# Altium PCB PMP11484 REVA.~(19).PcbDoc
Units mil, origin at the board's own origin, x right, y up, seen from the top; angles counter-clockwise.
Board outline 2400 x 2250 mil, 2 copper layers (Top Layer, Bottom Layer), stack 62 mil thick; 51 components, 24 nets, 109 pads, 73 vias.
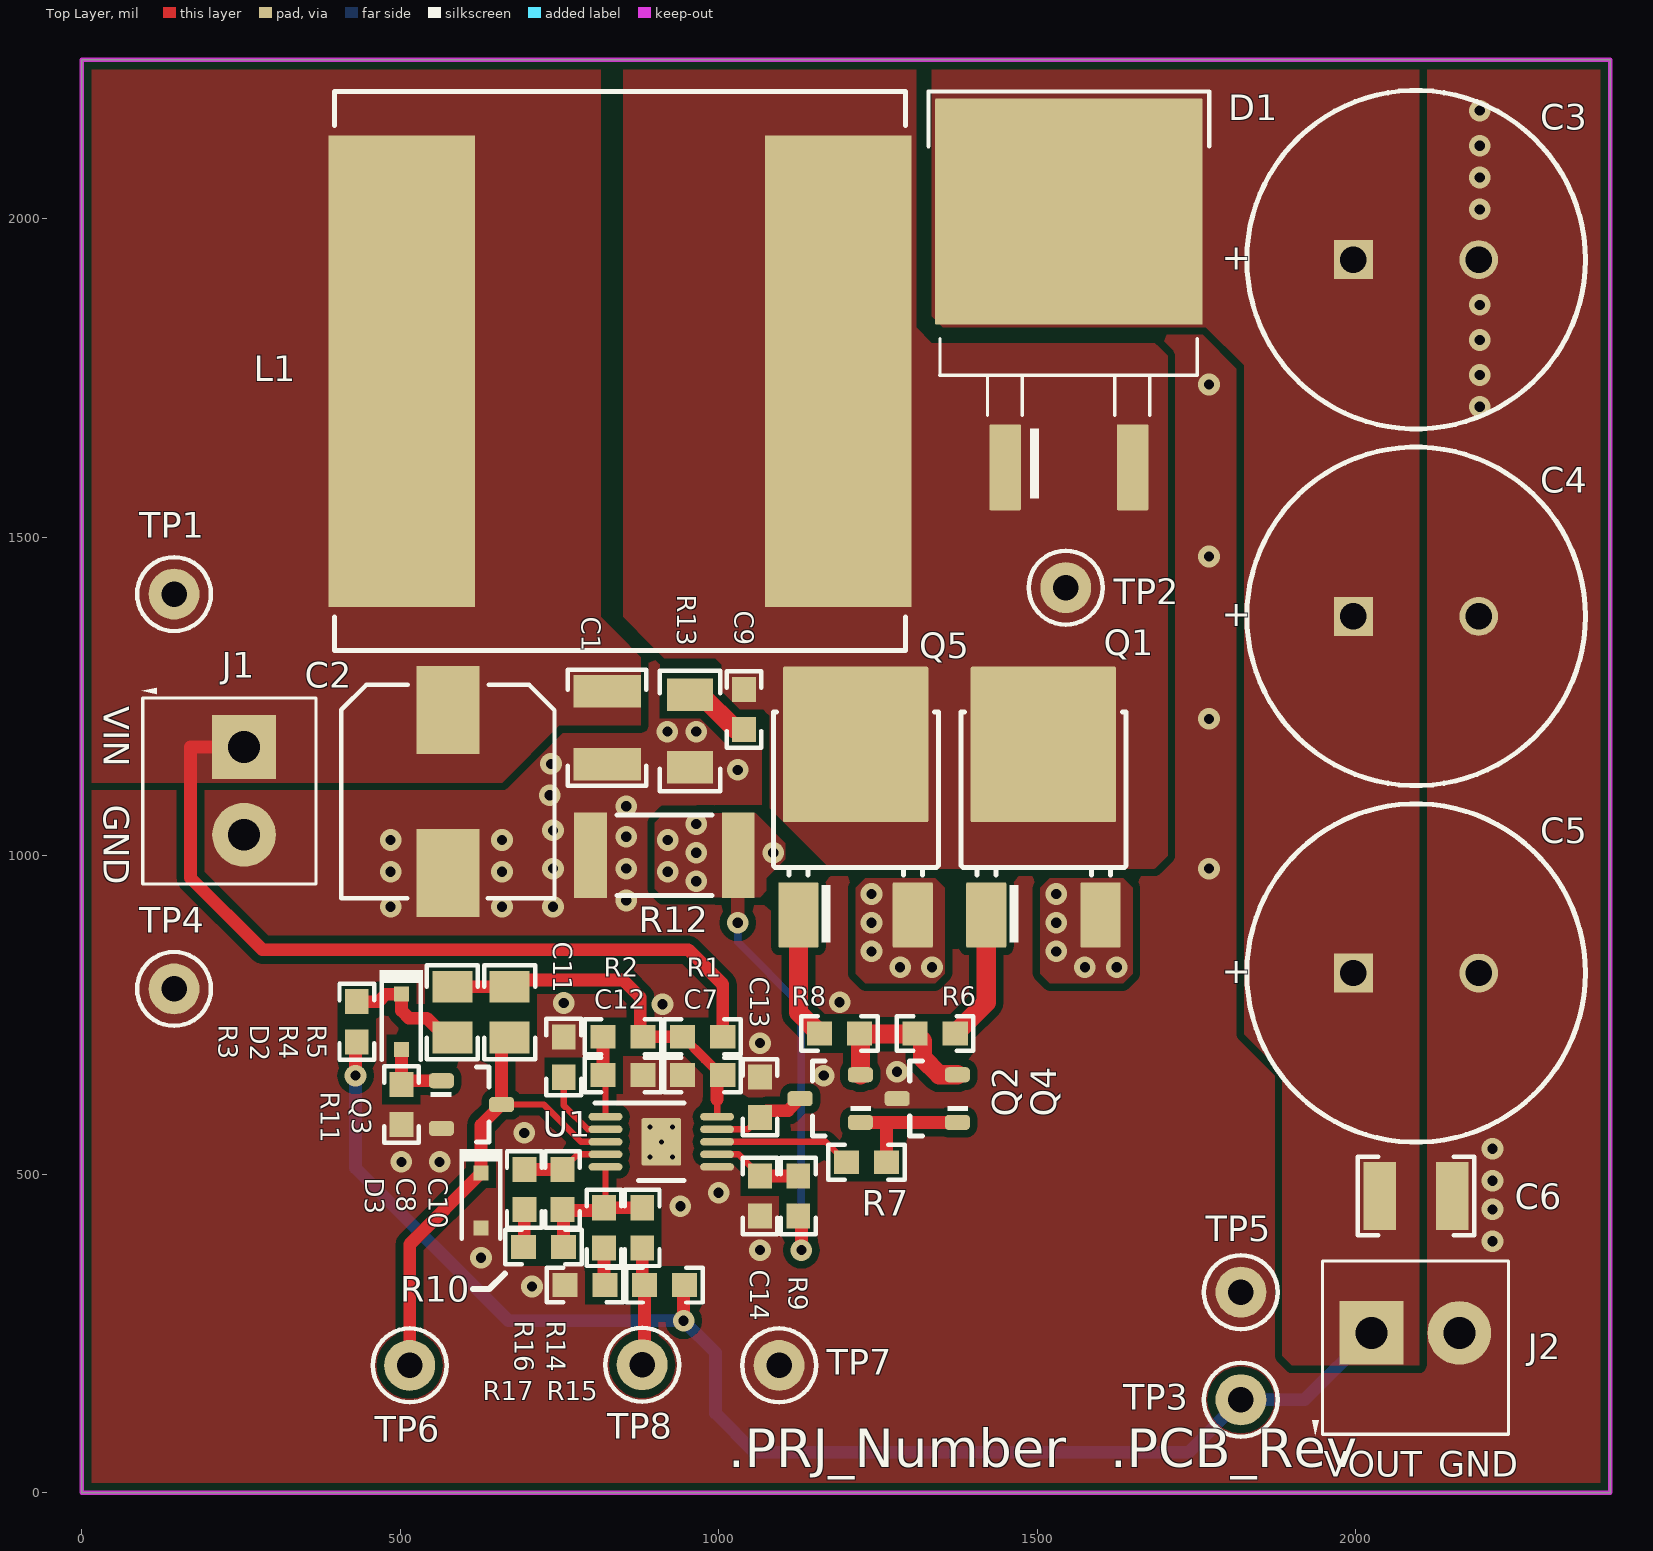
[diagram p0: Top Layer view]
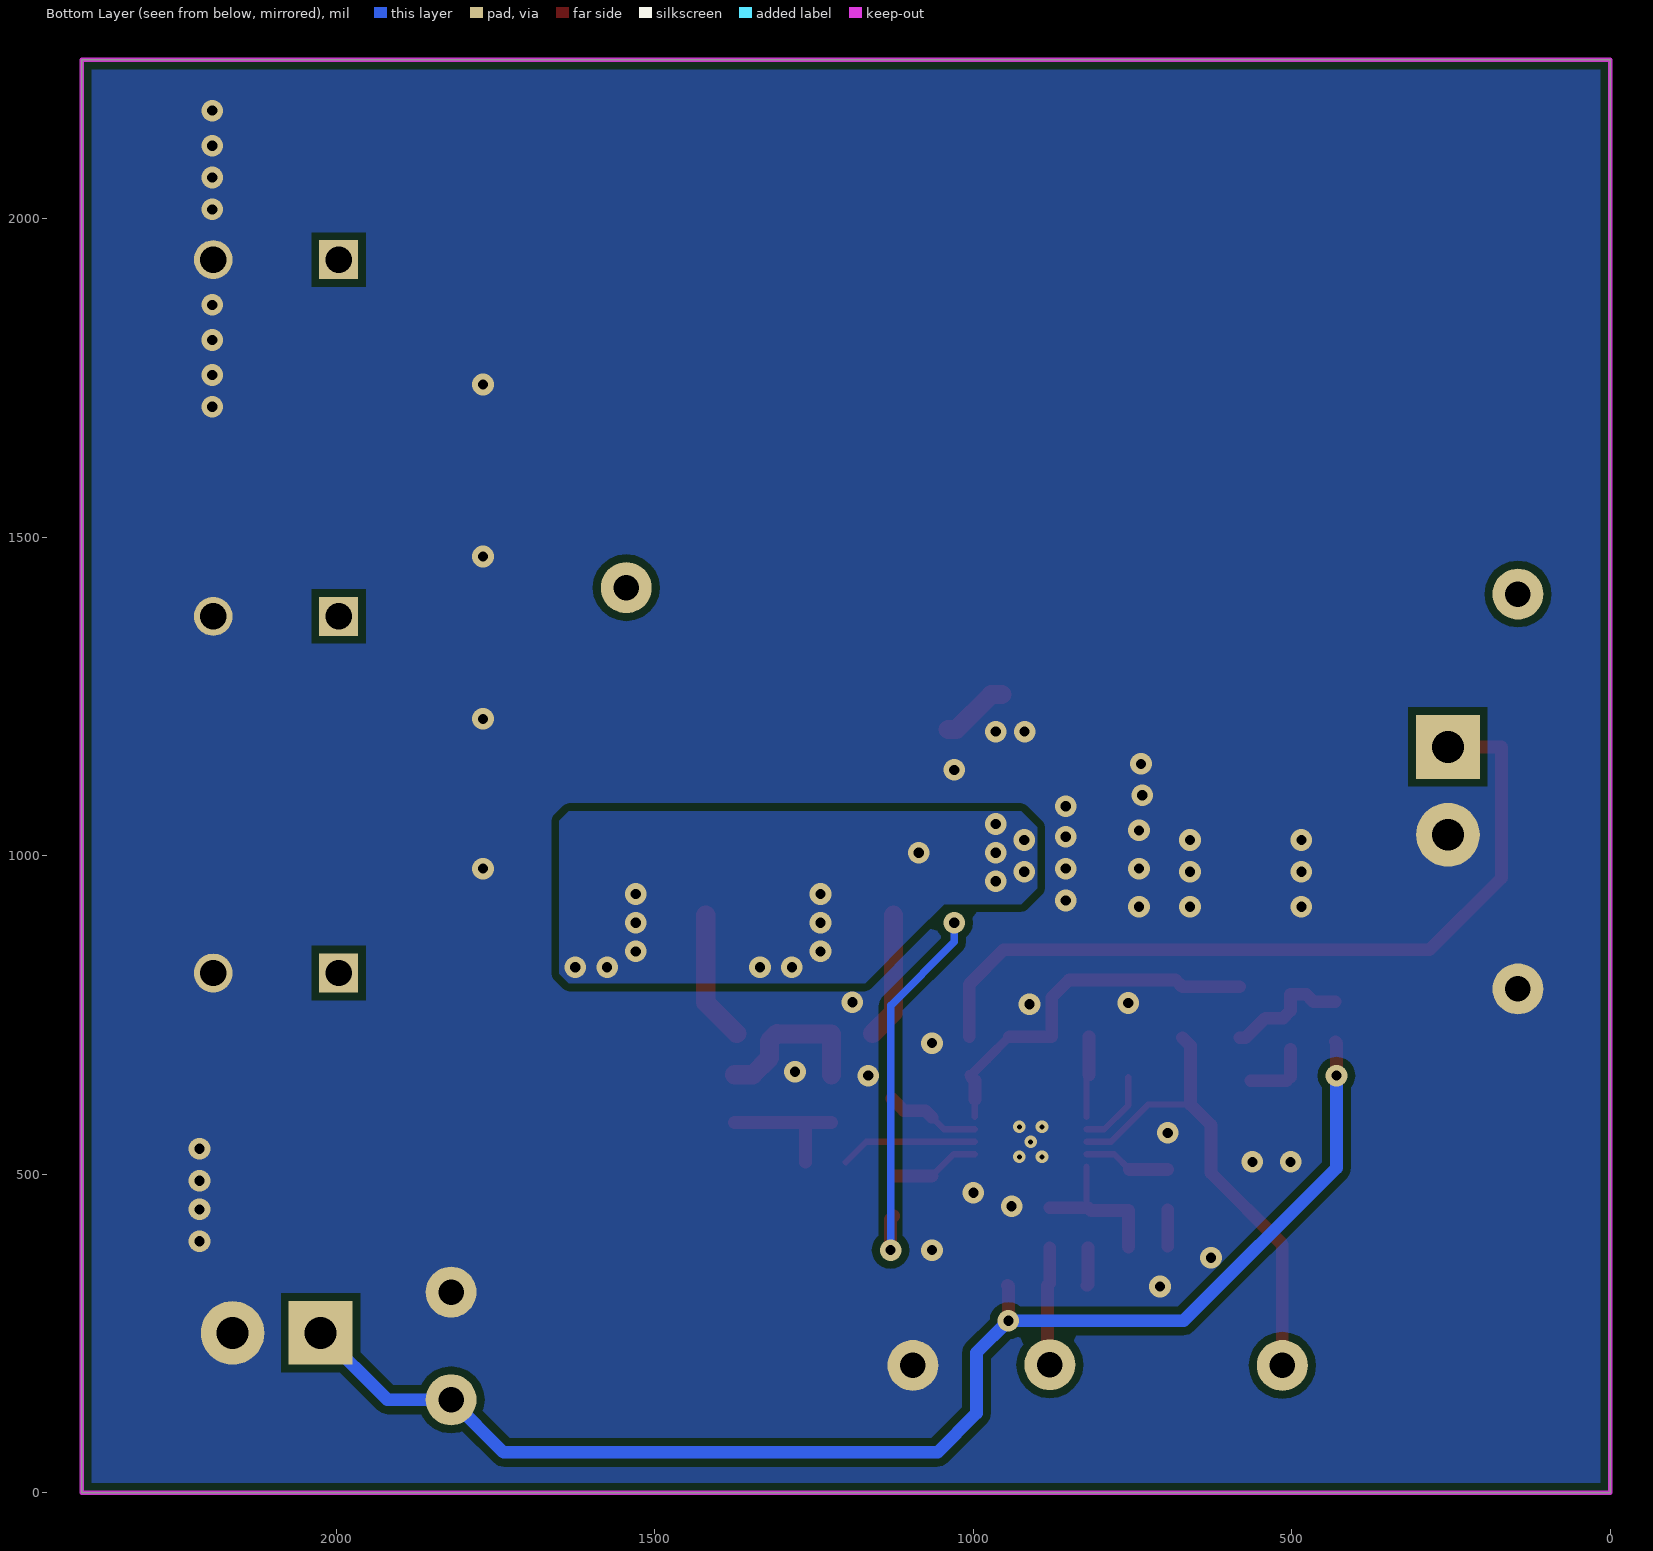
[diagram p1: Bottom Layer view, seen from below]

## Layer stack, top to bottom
Top Solder: solder mask 0.4, Solder Resist, Dk 3.5
Top Layer: signal copper 1.4
Dielectric1: core 59.2, FR-4, Dk 4.8
Bottom Layer: signal copper 1.4
Bottom Solder: solder mask 0.4, Solder Resist, Dk 3.5

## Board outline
0,0 2400,0 2400,2250 0,2250

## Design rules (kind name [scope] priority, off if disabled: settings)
AcuteAngle [All] p1: minimum=4.50000000000000E+0001 checktracksonly=FALSE
AssemblyTestPointUsage [All] p1: valid=2
Clearance Clearance_Keepouts [((IsTrack Or IsArc) And Not InPoly) And IsFree and IsKeepOut vs ((IsTrack Or IsArc) And Not InPoly) And IsFree and IsKeepOut] p1: gap=0
Clearance Clearance_BoardEdge_MountingHoles [OnCopper and InComponentClass('Mounting Holes') vs IsKeepOut] p2: gap=40
Clearance Clearance_BoardEdge_Poly [OnCopper and InPoly vs IsKeepOut] p3: gap=12
Clearance Clearance_BoardEdge [OnCopper and Not InComponentClass('Logo') and not InComponentClass('FiducialMark') and not InRegion(1000,500,4000,800) and Not IsKeepout vs IsKeepOut] p4: gap=50
Clearance Clearance_Poly [InPolygon] p5: gap=12
Clearance [All] p6: gap=7.87
ComponentClearance ComponentClearance_MountingHoles_FiducialMarks [InComponentClass('Mounting Holes') vs InComponentClass('FiducialMark')] p1: gap=50 collisioncheckmode=3 verticalgap=10 showdistances=FALSE
ComponentClearance ComponentClearance_Shunt [InComponentClass('Header') vs InComponentClass('Shunt')] p2: gap=0 collisioncheckmode=3 verticalgap=0 showdistances=FALSE
ComponentClearance ComponentClearance_Logo [InComponentClass('Logo')] p3: gap=50 collisioncheckmode=3 verticalgap=10 showdistances=FALSE
ComponentClearance ComponentClearance_ScrewToNut [(HasFootprint('NY PMS 440 0025 PH')) vs (HasFootprint('Keystone_1902C'))] p4: gap=5 collisioncheckmode=3 verticalgap=10 showdistances=FALSE
ComponentClearance ComponentClearance_MountingHoles [InComponentClass('Mounting Holes')] p5: gap=250 collisioncheckmode=3 verticalgap=100000 showdistances=FALSE
ComponentClearance ComponentClearance_SmallPassives [HasFootprint('0201*') or HasFootprint('0402*') or HasFootprint('0508') or HasFootprint('0603*') or HasFootprint('0612') or HasFootprint('0805*') or HasFootprint('0815*') or HasFootprint('0830*') or HasFootprint('1206*') or HasFootprint('1210*') or HasFootprint('1808*') or HasFootprint('1812*') or HasFootprint('1825*') or HasFootprint('2010*') or HasFootprint('2220*') or HasFootprint('2225*') or HasFootprint('2512*') or HasFootprint('2728*') or HasFootprint('3518*') vs HasFootprint('0201*') or HasFootprint('0402*') or HasFootprint('0508') or HasFootprint('0603*') or HasFootprint('0612') or HasFootprint('0805*') or HasFootprint('0815*') or HasFootprint('0830*') or HasFootprint('1206*') or HasFootprint('1210*') or HasFootprint('1808*') or HasFootprint('1812*') or HasFootprint('1825*') or HasFootprint('2010*') or HasFootprint('2220*') or HasFootprint('2225*') or HasFootprint('2512*') or HasFootprint('2728*') or HasFootprint('3518*')] p6: gap=15 collisioncheckmode=3 verticalgap=10 showdistances=FALSE
ComponentClearance ComponentClearance_THtoSMT [IsThruComponent vs IsSMTComponent] p7: gap=25 collisioncheckmode=3 verticalgap=30 showdistances=FALSE
ComponentClearance ComponentClearance_THtoTH [IsThruComponent vs IsThruComponent] p8: gap=25 collisioncheckmode=3 verticalgap=30 showdistances=FALSE
ComponentClearance [All] p9: gap=15 collisioncheckmode=3 verticalgap=10 showdistances=FALSE
DiffPairsRouting [All] p1: maxlimit=100 minlimit=10 mostfreqgap=10 toplayer_minwidth=15 toplayer_maxwidth=15 toplayer_prefwidth=15 bottomlayer_minwidth=15 bottomlayer_maxwidth=15 bottomlayer_prefwidth=15 maxuncoupledlength=1000
FabricationTestPointUsage TestPointUsage [All] p1: valid=2 allowmultiple=FALSE
FabricationTestpoint Testpoint [All] p1: side=3 testpointundercomponent=TRUE minsize=40 maxsize=100 preferedsize=60 minholesize=0 maxholesize=40 preferedholesize=32 testpointgrid=1 allowsidetop=TRUE allowsidebottom=TRUE usegrid=TRUE gridtolerance=0.01
FanoutControl Fanout_LCC [IsLCC] p1: bgadir=Out bgaviamode=Centered fanoutstyle=Auto fanoutdirection=Alternating viagrid=1 // Fanout_LCC (Default Rule)
FanoutControl Fanout_BGA [IsBGA] p2: bgadir=Out bgaviamode=Centered fanoutstyle=Auto fanoutdirection=Alternating viagrid=1 // Fanout_BGA (Default Rule)
FanoutControl Fanout_Default [All] p4: bgadir=Out bgaviamode=Centered fanoutstyle=Auto fanoutdirection=Alternating viagrid=1 // Fanout_Default (Default Rule)
FanoutControl Fanout_Small [(CompPinCount < 5)] p5: bgadir=Out bgaviamode=Centered fanoutstyle=Auto fanoutdirection=OutThenIn viagrid=1 // Fanout_Small (Default Rule)
HoleSize [All] p1: absolutevalues=TRUE maxlimit=251 minlimit=8 maxpercent=80.000 minpercent=20.000
MinimumAnnularRing MinimumAnnularRing_ThermalPadVias [IsVia and InAnyComponent] p1: minimumring=5.91
MinimumAnnularRing [All] p2: minimumring=9
MinimumSolderMaskSliver MinimumSolderMaskSliver_Logo [InComponentClass('Logo') vs InComponentClass('Logo')] p1: minsoldermaskwidth=0.7
MinimumSolderMaskSliver [All] p2: minsoldermaskwidth=3.94
PlaneClearance [All] p1: clearance=12
PlaneConnect [All] p1: planeconnectstyle=Direct reliefexpansion=10 reliefentries=4 reliefconductorwidth=10 reliefairgap=10
PolygonConnect [All] p1: connectstyle=Direct reliefconductorwidth=10 reliefentries=4 polygonreliefangle="90 Angle" airgapwidth=10
RoutingVias ThermalPadVias [IsVia and InAnyComponent] p1: holewidth=7.87 width=19.68 viastyle="Through Hole" minholewidth=7.87 minwidth=19.68 maxholewidth=12.99 maxwidth=23.62
RoutingVias [All] p2: holewidth=16 width=34 viastyle="Through Hole" minholewidth=7.87 minwidth=26 maxholewidth=40 maxwidth=65
SilkToBoardRegionClearance [Not ((IsComment or IsDesignator) And (Hide <> 'False')) and not InRegion(1000,500,4000,800)] p1:
SilkToSilkClearance SilkToSilkClearance_Pb-FreeLogo [(HasFootprint('Pb-Free_Overlay_Medium') OR HasFootprint('Pb-Free_Overlay_Small')) vs (HasFootprint('Pb-Free_Overlay_Medium') OR HasFootprint('Pb-Free_Overlay_Small'))] p1: silktosilkclearance=0
SilkToSilkClearance [All] p2: silktosilkclearance=0
SilkToSolderMaskClearance SilkToComonentPadClearance [IsPad and InAnycomponent] p1: minsilkscreentomaskgap=0 clearancetoexposedcopper=TRUE
SilkToSolderMaskClearance "Silk to Solder Mask Opening" [All] p2: minsilkscreentomaskgap=0 clearancetoexposedcopper=FALSE
SolderMaskExpansion [All] p1: expansion=1.97
UnpouredPolygon [All] p1: allowunpoured=FALSE
Width [All] p1: maxlimit=100 minlimit=6 preferedwidth=10 checkconnectedcopper=TRUE
13 further rules are at their usual default settings.

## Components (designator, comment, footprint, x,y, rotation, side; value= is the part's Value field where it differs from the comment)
C1 "C3225X7R1H475M250AB" 1210 825,1201.02 r90 top
C2 "EEHZA1H680P" SM_RADIAL_8MM 575,1101.02 r270 top
C3 "UBT1K221MHD1TO" BT_1250x2500 2095,1936.02 r0 top
C4 "UBT1K221MHD1TO" BT_1250x2500 2095,1376.02 r0 top
C5 "UBT1K221MHD1TO" BT_1250x2500 2095,816.02 r0 top
C6 "GRM32ER72A225KA35L" 1210 2095,466.02 r0 top
C7 "C1608X7R1H104K" 0603 975,656.02 r180 top
C8 "C1608X7R1H104K" 0603 695,476.02 r270 top
C9 "C1608C0G2A102J" 0603 1040,1230 r270 top
C10 "C1608C0G1H331J" 0603 755,476.02 r90 top
C11 "C1608X7R1H104K" 0603 756.98,683.93 r90 top
C12 "C1608C0G1H331J" 0603 850,656.02 r0 top
C13 "C1608X7R1C105K" 0603 1065,621.02 r90 top
C14 "C1608C0G1H331J" 0603 1065,466.02 r270 top
D1 "NRVBB1060T4G" DDPAK 1550,1856.02 r90 top
D2 "MMSZ5230BS-7-F" sod-323 501.98,739.54 r270 top
D3 "MMSZ5230BS-7-F" sod-323 626.98,458.93 r270 top
J1 "ED555/2DS" TERM_BLK_ED555-2DS 255,1171.02 r270 top
J2 "ED555/2DS" TERM_BLK_ED555-2DS 2025,251.02 r0 top
L1 "IHLP8787MZER220M5A" IHLP8787MZ 845,1761.02 r0 top
Q1 "IPD50N06S4L-12" DPAK 1510,1041.02 r90 top
Q2 "MMBT2222A" SOT-23 1175.28,618.91 r180 top
Q3 "MMBT2222A" SOT-23 611.98,609.54 r0 top
Q4 "MMBT2907A" SOT-23 1327.64,618.91 r180 top
Q5 "IPD50N06S4L-12" DPAK 1215,1041.02 r90 top
R1 "CRCW06034R70JNEA" 0603 975,716.02 r0 top
R2 "CRCW0603348KFKEA" 0603 850,716.02 r0 top
R3 "CRCW0603402KFKEA" 0603 431.98,739.54 r270 top
R4 "CRCW080520K0FKEA" 0805_HV 581.98,754.54 r90 top
R5 "CRCW080520K0FKEA" 0805_HV 671.98,754.54 r90 top
R6 "CRCW06030000Z0EA" 0603 1340,721.02 r0 top
R7 "CRCW06034R70JNEA" 0603 1231.98,518.93 r0 top
R8 "CRCW06030000Z0EA" 0603 1190,721.02 r180 top
R9 "CRCW06031K00FKEA" 0603 1125,466.02 r90 top
R10 "CRCW0603147KFKEA" 0603 725,386.02 r0 top
R11 "CRCW060310K0FKEA" 0603 501.98,609.54 r90 top
R12 "WSL25127L000FEA" 2512 915,1001.02 r0 top
R13 "CRCW12064R70JNEA" 1206 955,1196.02 r90 top
R14 "CRCW0603100KFKEA" 0603 880,416.02 r90 top
R15 "CRCW060349R9FKEA" 0603 915,326.02 r180 top
R16 "CRCW06032K10FKEA" 0603 820,416.02 r90 top
R17 "CRCW060329R4FKEA" 0603 790,326.02 r0 top
TP1 "5000" Keystone5000 145,1411.02 r0 top
TP2 "5000" Keystone5000 1545,1421.02 r0 top
TP3 "5000" Keystone5000 1820,146.02 r0 top
TP4 "5001" Keystone5001 145,791.02 r0 top
TP5 "5001" Keystone5001 1820,315 r0 top
TP6 "5000" Keystone5000 515,200 r0 top
TP7 "5001" Keystone5001 1095,200 r0 top
TP8 "5000" Keystone5000 880,201.02 r0 top
U1 "TPS40210DGQR" DGQ0010D_N 910,551.02 r0 top

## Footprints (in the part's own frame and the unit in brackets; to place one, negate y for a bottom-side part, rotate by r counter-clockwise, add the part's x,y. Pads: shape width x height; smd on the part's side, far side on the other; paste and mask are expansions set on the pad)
0603 [mm] "0603 from SM-752 data"
  rect 1x0.95 smd: 1(-0.8,0) 2(0.8,0)
  silkscreen extent -1.52,-0.69 1.52,0.69, body extent -0.87,-0.47 0.87,0.47, height 1
0805_HV [mil] "0805 with 30mil clearance between pads"
  rect 50x63 smd: 1(-40,0) 2(40,0)
  silkscreen extent -74,-40 74,40, body extent -43,-29 43,29, height 57
1206 [mm] "1206 from SM-752 data"
  rect 1.3x1.85 smd: 1(-1.45,0) 2(1.45,0)
  silkscreen extent -2.4,-1.21 2.4,1.21, body extent -1.7,-0.9 1.7,0.9, height 1.35
1210 [mm] "1210 from SM-752 data"
  rect 1.3x2.7 smd: 1(-1.45,0) 2(1.45,0)
  silkscreen extent -2.32,-1.57 2.32,1.57, body extent -1.7,-1.35 1.7,1.35, height 1.35
2512 [mm] "Chip Resistor, Body 6.3x3.2mm, IPC Medium Density"
  rect 1.3x3.4 smd: 1(-2.95,0) 2(2.95,0)
  silkscreen extent -1.9,-1.6 1.9,1.6, body extent -3.22,-1.67 3.22,1.67, height 0.71
BT_1250x2500 [mm] "TH, 2-Leads, Dia 12.5mm, Lead Sapcing 5mm"
  rect 1.55x1.55 hole 1.05: 1(-2.5,0)
  round 1.55 hole 1.05: 2(2.5,0)
  silkscreen extent -6.75,-6.75 6.75,6.75, body extent -6.7,-6.74 6.73,6.74, height 27.01
DDPAK [mil] "D2-PAK, 3-Pads, Body 9.7x10.4mm (max), TO-263AB, using Vishay Silionix recommended pad sizes"
  rrect8% 135x49.49 smd: 1(-246.06,100) 3(-246.06,-100)
  rrect1% 355x420 smd paste-181.1: 4(155.51,0)
  silkscreen extent -295,-220 344,220, body extent -295,-202 324,202, height 180
DGQ0010D_N [mm] "TSSOP, 10-Leads, Body 3x3mm, Pitch 0.5mm, Thermal Pad 1.88x1.57mm, IPC Medium Density"
  rrect100% 1.35x0.3 smd: 1(-2.225,1) 2(-2.225,0.5) 3(-2.225,0) 4(-2.225,-0.5) 5(-2.225,-1) 6(2.225,-1) 7(2.225,-0.5) 8(2.225,0) 9(2.225,0.5) 10(2.225,1)
  rrect6% 1.57x1.88 smd: 11(0,0)
  silkscreen extent -2.65,-1.55 0.9,1.55, body extent -2.46,-1.5 2.46,1.5, height 1.1
DPAK [mm] "D-PAK, 3-Pads, Body 6.22x6.73mm (max), TO-252AA using nominal STEP model"
  rrect6% 2.6x1.6 smd: 1(-3.4,2.28) 3(-3.4,-2.28)
  rrect2% 6.2x5.8 smd paste-2.9: 4(3.4,0)
  silkscreen extent -4.5,-3.3 4.7,3.28, body extent -3.86,-3.29 5.84,3.29, height 2.48
IHLP8787MZ [mm] "SMD, 2-Leads, Body 22x22.48mm"
  rect 5.84x18.8 smd: 1(-8.7,0) 2(8.7,0)
  silkscreen extent -11.39,-11.15 11.39,11.15, body extent -11.39,-11.15 11.39,11.15, height 13
Keystone5000 [mil] "For Keystone 500x miniature loop terminals"
  round 80 hole 40: 1(0,0)
  silkscreen extent -58,-58 58,58, body extent -49,-49 49,49, height 182
Keystone5001 [mil] "For Keystone 500x miniature loop terminals"
  round 80 hole 40: 1(0,0)
  silkscreen extent -58,-58 58,58, body extent -49,-49 49,49, height 182
SM_RADIAL_8MM [mm] "Nichicon 8x10"
  rect 3.5x2.5 smd: 1(-3.25,0) 2(3.25,0)
  silkscreen extent -4.25,-4.25 4.25,4.25, body extent -4.26,-4.26 4.26,4.26, height 10.5
sod-323 [mm] "NXP recommended land pattern"
  rect 0.6x0.6 smd paste-0.05: 1(-1.1,0) 2(1.1,0)
  silkscreen extent -2.06,-0.86 1.53,0.86, body extent -1.3,-0.67 1.3,0.68, height 1.1
SOT-23 [mm] "SOT23, 3-Leads, Body 2.9x1.3mm, Pitch 0.95mm, Lead Span 2.5mm, IPC Medium Density"
  rrect50% 1x0.6 smd: 1(-1.2,0.95) 2(-1.2,-0.95) 3(1.2,0)
  silkscreen extent -1.63,-1.5 0.7,1.5, body extent -1.16,-1.45 1.21,1.45, height 1
TERM_BLK_ED555-2DS [mil]
  rect 100x100 hole 50: 1(0,0)
  round 100 hole 50: 2(138,0)
  silkscreen extent -93,-161 215,113, body extent -69,-150 207,106, height 323

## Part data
C1: library part C3225X7R1H335M, "CAP, CERM, 4.7uF, 50V, +/-20%, X7R, 1210"
C2: "CAP, Polymer Hybrid, 68 µF, 50 V, +/- 20%, 30 ohm, 8x10 SMD"
C3 C4 C5: library part UBT1H471MHD1TO, "CAP, AL, 220 µF, 80 V, +/- 20%, 0.180 ohm, 1.24A, AEC-Q200 Grade 1, TH"
C6: "CAP, CERM, 2.2 µF, 100 V, +/- 10%, X7R, 1210"
C7 C8 C11: "CAP, CERM, 0.1uF, 50V, +/-10%, X7R, 0603"
C9: "CAP, CERM, 1000 pF, 100 V, +/- 5%, C0G/NP0, 0603"
C10 C12 C14: "CAP, CERM, 330 pF, 50 V, +/- 5%, C0G/NP0, 0603"
C13: "CAP, CERM, 1uF, 16V, +/-10%, X7R, 0603"
D1: library part MBRB2515LT4G, "Diode, Schottky, 60V, 10A, DDPAK"
D2 D3: "Diode, Zener, 4.7 V, 200 mW, SOD-323"
J1 J2: "Terminal Block, 6A, 3.5mm Pitch, 2-Pos, TH"
L1: library part IHLP8787MZE470M51, "Inductor, Shielded, 22 µH, 16 A, 0.0106 ohm, SMD"
Q1 Q5: library part IPD50R280CE, "MOSFET, N-CH, 60 V, 0.012 Ohms, AEC-Q101, DPAK"
Q2 Q3: library part "MMBT2222A, Fairchild Semiconductor", "Transistor, NPN, 40 V, 0.15 A, SOT-23"
Q4: library part "MMBT2907A, Fairchild Semiconductor", "Transistor, PNP, 60 V, 0.8 A, SOT-23"
R1 R7: "RES, 4.7 ohm, 5%, 0.1W, 0603"
R2: "RES, 348 k, 1%, 0.1 W, 0603"
R3: "RES, 402 k, 1%, 0.1 W, 0603"
R4 R5: "RES, 20.0 k, 1%, 0.125 W, 0805"
R6 R8: "RES, 0, 5%, 0.1 W, 0603"
R9: "RES, 1.00k ohm, 1%, 0.1W, 0603"
R10: "RES, 147 k, 1%, 0.1 W, 0603"
R11: "RES, 10.0 k, 1%, 0.1 W, 0603"
R12: library part WSL25129L000FEA18, "RES, 0.007, 1%, 2 W, 2512"
R13: "RES, 4.7, 5%, 0.25 W, 1206"
R14: "RES, 100k ohm, 1%, 0.1W, 0603"
R15: "RES, 49.9 ohm, 1%, 0.1W, 0603"
R16: "RES, 2.10 k, 1%, 0.1 W, 0603"
R17: "RES, 29.4, 1%, 0.1 W, 0603"
TP1 TP2 TP3 TP6 TP8: "Test Point, Miniature, Red, TH"
TP4 TP5 TP7: "Test Point, Miniature, Black, TH"
U1: "4.5-V TO 52-V INPUT CURRENT MODE BOOST CONTROLLER, DGQ0010D"

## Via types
v1: diameter 34, hole 16, Top Layer to Bottom Layer, 68 vias
v2: diameter 19.68, hole 7.87, Top Layer to Bottom Layer, 5 vias

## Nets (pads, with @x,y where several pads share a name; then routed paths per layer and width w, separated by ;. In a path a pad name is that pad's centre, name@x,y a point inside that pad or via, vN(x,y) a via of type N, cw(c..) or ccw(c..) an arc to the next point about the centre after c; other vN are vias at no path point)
GND: C1.1 C2.2 C3.2 C4.2 C5.2 C6.2 C7.2 C11.2 C12.2 C13.2 C14.2 D3.2 J1.2 J2.2 Q3.2 Q4.3 R11.1 R12.1 R13.1 R17.1 TP4.1 TP5.1 TP7.1 U1.6 U1.11
  other v1: 706.98,323.93 626.98,368.93 1065,381.02 2215,395 2215,445 940,450 1000,471.02 2215,490 501.98,519.54 561.98,519.54 2215,540 695,565 1165,655 1280,661.02 1065,706.02 912,767.02 756.98,768.93 1190,770 485,920 660,920 740,920 855,930 485,975 660,975 740,980 855,980 1770,980 485,1025 660,1025 855,1030 740,1040 855,1077.8 735,1095 1030,1135 736.95,1144.42 919.57,1195 965,1195 1770,1215 1770,1470 2195,1705 1770,1740 2195,1755 2195,1810 2195,1865 2195,2015 2195,2065 2195,2115 2195,2170
  other v2: 892.28,527.4 927.72,527.4 910,551.02 892.28,574.65 927.72,574.65
NetC1_2: C1.2 C2.1 J1.1 L1.1 R1.2 TP1.1 | length 1276.7
  Top Layer w20: J1.1 171.02,1171.02 171.02,965.35 283.84,852.54 952.46,852.54 1006.5,798.5 R1.2
NetC7_1: C7.1 R1.1 R2.2 R4.2 R5.2 U1.10 | length 592
  Top Layer w10: U1.10 997.6,617.6
  Top Layer w15: R1.1 943.63,716.02 978.56,681.09 978.56,680.96 1003.5,656.02 C7.1
  Top Layer w20: R4.2 R5.2 682.44,805 850,805 877.13,777.87 877.13,716.02 R2.2 R1.1 ; 997.6,617.6 997.6,647.13 C7.1@1003.5,653.03
NetC8_1: C8.1 C10.2 U1.4 | length 137.3
  Top Layer w10: C10.2 778.82,531.34 U1.4
  Top Layer w20: C8.1 C10.2
NetC8_2: C8.2 R10.1 | length 57
  Top Layer w20: R10.1@695,387.52 C8.2
NetC9_1: C9.1 D1.1 D1.3 L1.2 Q1.4 Q5.4 TP2.1
NetC9_2: C9.2 R13.2 | length 107.6
  Top Layer w30: R13.2 971.89,1253.11 1026.5,1198.5 C9.2
NetC10_1: C10.1 R10.2 R14.2 R16.2 U1.5 | length 247.5
  Top Layer w10: R16.2@815.51,443.03 R16.2 822.4,449.92 U1.5
  Top Layer w20: R10.2 756.5,443.03 R16.2@815.51,443.03 ; R16.2 R14.2
NetC11_1: C11.1 U1.2 | length 125.3
  Top Layer w10: C11.1 756.98,608.02 794.29,570.71 U1.2
NetC12_1: C12.1 R2.1 U1.1 | length 127.2
  Top Layer w10: C12.1 822.4,652.13 U1.1
  Top Layer w20: C12.1 R2.1
NetC13_1: C13.1 Q2.3 U1.9 | length 150.4
  Top Layer w10: U1.9 1046.18,570.71 C13.1
  Top Layer w20: C13.1 1075.47,600 1109.12,600 Q2.3
NetC14_1: C14.1 R9.2 U1.7 | length 141.4
  Top Layer w10: U1.7 1031.18,531.34 C14.1
  Top Layer w20: C14.1 R9.2
NetD2_1: D2.1 R3.1 R4.1 | length 198.3
  Top Layer w20: R3.1 466.03,771.03 477.84,782.84 D2.1 501.98,756.98 513.95,745 541.98,745 572.44,714.54 R4.1
NetD2_2: D2.2 Q3.1 R11.2 | length 100.2
  Top Layer w20: R11.2@501.98,652.84 D2.2 ; R11.2@507.88,646.94 Q3.1
NetD3_1: D3.1 Q3.3 R5.1 TP6.1 U1.3 | length 767
  Top Layer w10: Q3.3 725.46,609.54 783.98,551.02 U1.3
  Top Layer w20: TP6.1 515,390.26 D3.1 626.98,577.29 Q3.3 659.22,701.78 R5.1
NetQ1_1: Q1.1 R6.2 | length 206.3
  Top Layer w30: R6.2 1420.24,769.76 Q1.1
NetQ1_3: Q1.3 Q5.3 R9.1 R12.2 | length 611
  Top Layer w20: R9.1 1130,429.53 v1(1130,381.02)
  Bottom Layer w12: v1(1030,895) 1030,865 1130.02,764.98 v1(1130,381.02)
  other v1: 1285,825 1335,825 1575,825 1625,825 1240,850 1530,850 1240,895 1530,895 1240,940 1530,940 965,960 920,975 965,1005 1085.87,1005 920,1025 965,1050
NetQ2_1: Q2.1 Q4.1 R7.2 | length 213.4
  Top Layer w20: Q2.1 Q4.1 ; R7.2 1263.47,579.98
NetQ2_2: Q2.2 Q4.2 R6.1 R8.1 | length 260.9
  Top Layer w20: Q4.2@1373.57,655 Q4.2
  Top Layer w30: Q2.2 1222.52,720 1307.48,720 R6.1 1320,709.53 1320,682.65 1346.33,656.32 Q4.2
NetQ5_1: Q5.1 R8.2 | length 199.9
  Top Layer w30: Q5.1 1125.24,754.29 R8.2
NetR7_1: R7.1 U1.8 | length 216.2
  Top Layer w10: U1.8 1168.38,551.02 R7.1
NetR14_1: R14.1 R15.2 TP8.1 | length 186.4
  Top Layer w20: TP8.1 883.5,204.53 R15.2 880,329.53 R14.1
NetR16_1: R16.1 R17.2 | length 59.1
  Top Layer w20: R16.1 820,327.52 R17.2
VOUT: C3.1 C4.1 C5.1 C6.1 D1.4 J2.1 R3.2 R15.1 TP3.1 | length 2168.8
  Top Layer w20: v1(430,655) 430,706.06 R3.2 ; v1(945,270) 945,324.53 R15.1
  Bottom Layer w20: v1(430,655) 430,510 670,270 v1(945,270) 995,220 995,125 1056.5,63.5 1737.48,63.5 TP3.1 1920,146.02 J2.1

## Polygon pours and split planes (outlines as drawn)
GND on Top Layer "Top Layer-No Net 5" (solid, remove dead copper, pour order 21): 0,0 0,2250 2400,2250 2400,0
NetQ1_3 on Top Layer "Top Layer-No Net 6" (solid, remove dead copper, pour order 17): 1055,935 1065,935 1075,945 1075,949.25 1075,965 1105,995 1105,1020 1058.03,1066.97 915,1066.97 900,1051.97 900,965 900,948.03 910,938.03 912.95,935.08 1020,935.08 1020,890 1025,885 1035,885 1040,890 1040,935.08
NetQ1_3 on Top Layer "Top Layer-No Net 4" (solid, remove dead copper, pour order 13): 1335,800 1340,800 1355,815 1355,945 1355,950 1340,965 1235,965 1230,965 1215,950 1215,835 1215,815 1230,800
NetQ1_3 on Top Layer "Top Layer-No Net 3" (solid, remove dead copper, pour order 11): 1635,800 1650,815 1650,949.25 1650,950 1635,965 1525,965 1520,965 1505,950 1505,815 1520,800
VOUT on Top Layer "Top Layer-No Net 2" (solid, remove dead copper, pour order 7): 1343.74,1838.31 1335,1847.05 1335,1885 1335,2250 2100,2250 2100,2050 2100,200 1900,200 1885,215 1885,270 1885,660 1825,720 1825,910 1825,1730 1825,1770 1765,1830 1755,1830 1352.05,1830 1347.05,1835
NetC9_1 on Top Layer "Top Layer-No Net 1" (solid, remove dead copper, pour order 5): 850,2250 850,1900 850,1375 895,1330 915,1310 960,1310 995,1310 1005,1300 1005,1275 1005,1243 1019.01,1229 1061,1229 1071,1229 1075,1225 1080,1220 1080,1210 1080,1075 1115,1040 1175,980 1230,980 1632.33,980 1680,980 1685,980 1705,1000 1705,1090 1705,1780 1705,1785 1685,1805 1530,1805 1335,1805 1310,1830 1310,1860 1310,2250
NetC1_2 on Top Layer "Top Layer-No Net" (solid, remove dead copper, pour order 3): 0,2250 0,1115 660,1115 750,1205 878.15,1205 878.15,1311.85 870,1320 850,1340 815,1375 815,1555 815,2250
GND on Bottom Layer "Bottom Layer-No Net 1" (solid, remove dead copper, pour order 19): 0,0 0,2250 2400,2250 2400,0
NetQ1_3 on Bottom Layer "Bottom Layer-No Net" (solid, remove dead copper, pour order 9): 1635,800 1650,815 1650,820 1650,1055 1635,1070 1110,1070 925,1070 900,1045 900,975 900,949.25 925,924.25 1045,924.25 1045.75,924.25 1095,875 1170,800 1405,800

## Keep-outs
Keep-Out Layer:
  the board outline again, w7
  text ".Layer_Name" at 577,-858.49 h60

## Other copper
Top Layer:
  text ".Layer_Name" at 577,-858.49 h60
Bottom Layer:
  text ".Layer_Name" at 577,-858.49 h60

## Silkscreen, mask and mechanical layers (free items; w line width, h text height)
Top Overlay:
  lines w10: 615,320 640,320 663.98,343.98
  text "VIN" at 35,1235 h40 r270
  text "GND" at 35,1080 h40 r270
  text ".PRJ_Number" at 1015,40 h60
  text ".PCB_Rev" at 1615,40 h60
  text "VOUT" at 1950,25 h40
  text "GND" at 2130,25 h40
  text ".Layer_Name" at 577,-858.49 h60
Bottom Overlay:
  text ".Layer_Name" at 577,-858.49 h60
Top Paste:
  text ".Layer_Name" at 577,-858.49 h60
Bottom Paste:
  text ".Layer_Name" at 577,-858.49 h60
Top Solder:
  text ".Layer_Name" at 577,-858.49 h60
  text ".Layer_Name" at 577,-858.49 h60
Bottom Solder:
  text ".Layer_Name" at 577,-858.49 h60
Drill Guide:
  text ".Layer_Name" at 577,-858.49 h60
M1 Board Outline:
  lines w7: 0,0 0,2250 2400,2250 2400,0 0,0
  lines w10: 0,0 0,2250 2400,2250 2400,0 0,0
  text ".Layer_Name" at 577,-858.49 h60
M2 Board Dimensions:
  rectangle: 0,-275 125,-150
  rectangle: 125,-400 500,-275
  lines w7: 0,-275 1000,-275 ; 125,-400 125,-150 ; 250,-400 250,-150 ; 500,-400 500,-150 ; 750,-400 750,-150 ; 0,-400 1000,-400 1000,-150 0,-150 0,-400
  text ".Layer_Name" at 577,-858.49 h60
M3 3D STEP Top:
  text ".Layer_Name" at 577,-858.49 h60
M4 3D STEP Bottom:
  text ".Layer_Name" at 577,-858.49 h60
M5 Assembly Top:
  lines w10: -292,-930.17 6308,-930.17 ; -292,-726.83 6310,-726.83 ; -292,-523.5 -292,-1133.5 3713,-1133.5 6310,-1133.5 6310,-523.5 -291.5,-523.5 -291.5,-1133.5 1284,-1133.5 ; 2173,-1133.5 2173,-523.5 ; 3440,-726.83 3440,-523.5 ; 4280,-726.83 4280,-523.5 ; 4902,-1140 4902,-937.17
  text "COMPONENTS MARKED 'DNP' SHOULD NOT BE POPULATED." at 1153.5,-318.5 h60
  text "ASSEMBLY VARIANT:" at 1153,-434 h60
  text ".VariantName" at 2189,-434 h60
  text "PCB VIEWED FROM TOP SIDE" at -228.5,-655.67 h60
  text "BOARD #:" at 2248,-655.67 h60
  text ".PRJ_Number" at 2793.5,-655.67 h60
  text "REV:" at 3638,-655.67 h60
  text ".PCB_Rev" at 3929.5,-655.67 h60
  text "SVN REV:" at 4476,-655.67 h60
  text ".VersionControl_RevNumber" at 4982,-655.67 h60
  text "TID #:" at 2248,-859 h60
  text ".TID" at 2793.5,-859 h60
  text "PLOT NAME =" at -228.5,-1064.34 h60
  text ".plot_File_Name" at 577,-1064.34 h60
  text "GENERATED    :" at 2250,-1064.34 h60
  text ".Print_Date" at 3119.5,-1064.34 h60
  text ".Print_Time" at 3848.5,-1064.34 h60
  text "TEXAS INSTRUMENTS" at 5113,-1064.34 h60
M6 Assembly Bottom:
  lines w10: -292.5,-727.33 6309.5,-727.33 ; -290.5,-930.67 6309.5,-930.67 ; 1115.5,-1140.5 1115.5,-937.67 ; 1737.5,-727.33 1737.5,-524 ; 2577.5,-727.33 2577.5,-524 ; 3844.5,-1134 3844.5,-524 ; 4733.5,-1134 6309,-1134 6309,-524 -292.5,-524 -292.5,-1134 2304.5,-1134 6309.5,-1134 6309.5,-524
  text "COMPONENTS MARKED 'DNP' SHOULD NOT BE POPULATED." at 6102,-318 h60
  text ".VariantName" at 5058,-434 h60
  text "ASSEMBLY VARIANT:" at 6097,-434 h60
  text ".VersionControl_RevNumber" at 1035.5,-656.17 h60
  text "SVN REV:" at 1541.5,-656.17 h60
  text ".PCB_Rev" at 2088,-656.17 h60
  text "REV:" at 2379.5,-656.17 h60
  text ".PRJ_Number" at 3224,-656.17 h60
  text "BOARD #:" at 3769.5,-656.17 h60
  text "PCB VIEWED FROM BOTTOM SIDE" at 6246,-656.17 h60
  text ".TID" at 3224,-859.5 h60
  text "TID #:" at 3769.5,-859.5 h60
  text "TEXAS INSTRUMENTS" at 904.5,-1064.84 h60
  text ".Print_Time" at 2169,-1064.84 h60
  text ".Print_Date" at 2898,-1064.84 h60
  text "GENERATED    :" at 3767.5,-1064.84 h60
  text ".plot_File_Name" at 5440.5,-1064.84 h60
  text "PLOT NAME =" at 6246,-1064.84 h60
M9 Title Sheet:
  drawing of 57 lines, arcs and shapes, not listed
  text "1" at 739.84,8036.5 h70
  text "2" at 3235.5,8036.5 h70
  text "3" at 5724.84,8036.5 h70
  text "4" at 8231.51,8036.5 h70
  text "5" at 10730.5,8036.5 h70
  text "6" at 13235.5,8036.5 h70
  text "A" at -416.5,6893.5 h70
  text "A" at 14383.5,6893.5 h70
  text "B" at -416.5,4513.5 h70
  text "B" at 14383.5,4513.5 h70
  text "C" at -416.5,2138.5 h70
  text "C" at 14383.5,2138.5 h70
  text "PROJECT TITLE:" at 11343.5,277.5 h45
  text ".PRJ_Title" at 11393.5,144.17 h70
  text "DESIGNED FOR:" at 11343.5,-23.5 h45
  text ".PRJ_Customer" at 11393.5,-163.5 h70
  text "D" at -416.5,-231.5 h70
  text "D" at 14383.5,-231.5 h70
  text "FILE NAME:" at 11343.5,-323.5 h45
  text ".PCB_File_Name_No_Path" at 11393.5,-443.5 h70
  text "Texas Instruments (TI) and/or its licensors do not warrant the accuracy or completeness of this specification" at 6374,-605.34 h45
  text "ENGINEER:" at 11343.5,-613.5 h45
  text "LAYOUT BY:" at 12848.5,-613.5 h45
  text "or any information contained therein. TI and/or its licensors do not warrant that this design will meet" at 6329.01,-718 h45
  text ".PRJ_Engineer" at 11393.5,-768.49 h70
  text ".PCB_Layout" at 12899,-768.49 h70
  text "the specifications, will be suitable for your application or fit for any particular purpose, or will operate in" at 6329.01,-830.67 h45
  text ".Layer_Name" at 577,-858.49 h60
  text "ALTIUM DESIGNER VERSION:" at 12848.5,-923.5 h45
  text "an implementation. TI and/or its licensors do not warrant that the design is production worthy. You should" at 6329.01,-943.33 h45
  text "completely validate and test your design implementation to confirm the system functionality for your application." at 6374,-1056 h45
  text ".print_Scale" at 11393.5,-1056.83 h70
  text ".Application_BuildNumber" at 12899,-1056.83 h70
  text "1" at 739.84,-1263.5 h70
  text "2" at 3235.5,-1263.5 h70
  text "3" at 5724.84,-1263.5 h70
  text "4" at 8231.51,-1263.5 h70
  text "5" at 10730.5,-1263.5 h70
  text "6" at 13235.5,-1263.5 h70
M10 Fab Notes:
  drawing of 189 lines, arcs and shapes, not listed
  text "DESIGN INFORMATION" at 12381.02,6028 h60
  text "MIN. TRACK WIDTH:" at 11736.46,5848 h60
  text "8" at 12832.7,5848 h60
  text "MIL" at 12987.46,5848 h60
  text "MIN. CLEARANCE:" at 11736.46,5716 h60
  text "0.2" at 12772.7,5716 h60
  text "mm" at 12987.46,5716 h60
  text "MIN. VIA PAD SIZE:" at 11736.46,5584 h60
  text "24" at 12802.71,5584 h60
  text "MIL" at 12987.46,5584 h60
  text "0.05mm (2MIL)" at 12431.46,5442.29 h60
  text "MINIMUM ANNULAR RING" at 11407.23,5438 h60
  text "EXTERNAL" at 13139.46,5438 h60
  text "PER" at 11607.23,5320 h60
  text "IPC-D-275 CLASS 2 LEVEL C" at 11827.23,5320 h60
  text "MIL, HOLES" at 13315.46,5207.71 h60
  text "+/-" at 12923,5207 h60
  text "+/-" at 13777,5207 h60
  text "REGISTRATION TOLERANCES:" at 11407.23,5202 h60
  text "METAL" at 12607,5202 h60
  text "5" at 13183.2,5202 h60
  text "3" at 14016.2,5202 h60
  text "MIL" at 14132.46,5202 h60
  text "+/-" at 13777,5089 h60
  text "HOLE SIZE TOLERANCE (UNLESS OTHERWISE SPECIFIED):" at 11407.23,5084 h60
  text "3" at 14016.2,5084 h60
  text "MIL" at 14132.46,5084 h60
  text "MATERIAL:" at 11332.46,4874.54 h60
  text "FR-4 High Tg" at 12318.9,4734.21 h60
  text "FR-408" at 11753.46,4725.64 h60
  text "OTHER" at 13241.46,4725.64 h60
  text "X" at 12164,4722 h60
  text "62 MIL (1.6mm) +/-10%" at 12073.56,4562.92 h60
  text "THICKNESS:" at 11407.23,4558.64 h60
  text "X" at 11945.4,4558.64 h60
  text "OTHER" at 13358.46,4558.64 h60
  text "TOLERANCE:" at 11407.23,4400.64 h60
  text "X" at 12246.53,4400.64 h60
  text "ANSI IPC-6012 TYPE 3 CLASS 2" at 12433.48,4400.64 h60
  text "OTHER +/-" at 12433.46,4244.64 h60
  text "BOW & TWIST:" at 11407.23,4087.64 h60
  text "X" at 12246.53,4087.64 h60
  text "ANSI IPC-6012 TYPE 3 CLASS 2" at 12433.48,4087.64 h60
  text "OTHER +/-" at 12433.46,3929.13 h60
  text "DRILLING:" at 11332.46,3790.64 h60
  text "REFERENCE:" at 11407.23,3673.64 h60
  text "X" at 12055.46,3673.64 h60
  text "AS SHOWN" at 12242.46,3673.64 h60
  text "X" at 12956.46,3673.64 h60
  text "NC_DRILL FILES" at 13093.46,3673.64 h60
  text "PTH MIN COPPER THICKNESS:" at 11407.23,3515.64 h60
  text "X" at 12757.46,3515.64 h60
  text "1MIL" at 12894.46,3515.64 h60
  text "OTHER" at 13391.46,3515.64 h60
  text "BOARD FINISH:" at 11332.46,3356.64 h60
  text "SILKSCREEN:" at 11487.68,3238.64 h60
  text "X" at 12436.46,3238.64 h60
  text "TOP" at 12562.46,3238.64 h60
  text "X" at 12946.46,3238.64 h60
  text "BOTTOM" at 13073.46,3238.64 h60
  text "SILKSCREEN COLOR:" at 11487.68,3071.64 h60
  text "X" at 12435.42,3071.64 h60
  text "WHITE" at 12562.46,3071.64 h60
  text "OTHER" at 13073.46,3071.64 h60
  text "X" at 12566.42,2912.44 h60
  text "GREEN" at 12693.46,2912.44 h60
  text "OTHER" at 13311.46,2912.44 h60
  text "SOLDER RESIST COLOR:" at 11487.68,2901.64 h60
  text "X" at 12566.42,2742.44 h60
  text "MATTE" at 12693.46,2742.44 h60
  text "SEMI-GLOSS" at 13311,2741.8 h60
  text "IMMERSION GOLD (ENIG)" at 12393.46,2553.92 h60
  text "ENEPIG" at 13731,2550.64 h60
  text "SURFACE FINISH:" at 11332.46,2549.64 h60
  text "X" at 12206.51,2549.64 h60
  text "IMM. TIN/SILVER OR EQUIV" at 11662,2392.64 h60
  text "OTHER" at 13093.46,2392.64 h60
  text "ARRAY/PANEL:" at 11332.46,2213.64 h60
  text "CUT AND TRIM PER M1 BOARD OUTLINE" at 12393.46,2209.35 h60
  text "N.C. ROUTE" at 12393.46,2057.64 h60
  text "X" at 13072.46,2057.64 h60
  text "V. SCORE" at 13259.46,2057.64 h60
  text "CERTIFICATION:" at 11332.46,1920.64 h60
  text "MATERIALS AND WORKMANSHIP FOR ALL PCBS" at 12057.46,1920.64 h60
  text "TO MEET OR EXCEED THE REQUIREMENTS OF:" at 12057.46,1822.64 h60
  text "X" at 11683.96,1686.13 h60
  text "ANSI IPC-A-600F CLASS ->" at 11822.96,1686.13 h60
  text "X" at 13462.02,1686.13 h60
  text "2" at 13580.96,1686.14 h60
  text "1" at 13265.96,1684.64 h60
  text "3" at 13934.96,1684.64 h60
  text "X" at 11686.02,1526.64 h60
  text "UL 94V-0" at 11822.96,1526.64 h60
  text "X" at 12498.02,1526.64 h60
  text "RoHS" at 12634.96,1526.64 h60
  text "OTHER" at 13279.36,1526.64 h60
  text "PER ORDER" at 13676.42,1526.64 h60
  text "ADDITIONAL REQUIREMENTS:" at 11332.46,1385.64 h60
  text "MICROSECTION:" at 11407.23,1270.64 h60
  text "YES" at 12312.96,1270.64 h60
  text "REQUIRED" at 13174.46,1114.49 h60
  text "BARE BOARD ELEC. TEST:" at 11407.23,1111.64 h60
  text "NONE" at 12712.96,1111.64 h60
  text "X" at 13047.46,1111.64 h60
  text "PER ORDER" at 13766.46,1111.64 h60
  text "MANUFACTURER'S UL:" at 11407.23,954.64 h60
  text "RAIL" at 12572.96,950.35 h60
  text "METAL" at 13064.77,950.35 h60
  text "X" at 13440,950 h60
  text "SILK" at 13576.46,950.35 h60
  text ".Layer_Name" at 577,-858.49 h60
M11 Gerber Information:
  lines w10: -292,-930.17 6308,-930.17 ; -292,-726.83 6310,-726.83 ; -292,-523.5 -292,-1133.5 3713,-1133.5 6310,-1133.5 6310,-523.5 -291.5,-523.5 -291.5,-1133.5 1284,-1133.5 ; 2173,-1133.5 2173,-523.5 ; 3440,-726.83 3440,-523.5 ; 4280,-726.83 4280,-523.5 ; 4902,-1140 4902,-937.17
  text "ALL ARTWORK VIEWED FROM TOP SIDE" at -228.5,-655.67 h60
  text "BOARD #:" at 2248,-655.67 h60
  text ".PRJ_Number" at 2793.5,-655.67 h60
  text "REV:" at 3638,-655.67 h60
  text ".PCB_Rev" at 3929.5,-655.67 h60
  text "SVN REV:" at 4476,-655.67 h60
  text ".VersionControl_RevNumber" at 4982,-655.67 h60
  text "LAYER NAME =" at -228.5,-858.49 h60
  text "TID #:" at 2248,-859 h60
  text ".TID" at 2793.5,-859 h60
  text "PLOT NAME =" at -228.5,-1064.34 h60
  text ".plot_File_Name" at 577,-1064.34 h60
  text "GENERATED    :" at 2250,-1064.34 h60
  text ".Print_Date" at 3119.5,-1064.34 h60
  text ".Print_Time" at 3848.5,-1064.34 h60
  text "TEXAS INSTRUMENTS" at 5113,-1064.34 h60
M12 Stackup:
  drawing of 191 lines, arcs and shapes, not listed
  text "Layer" at 9790.58,7830 h60
  text "Name" at 10200.49,7830 h60
  text "Material" at 11130.23,7830 h60
  text "Thickness" at 11990,7830 h60
  text "Constant" at 12639.84,7830 h60
  text "Board Layer Stack" at 13209.7,7830 h60
  text "1" at 9790.58,7710 h60
  text "Top Overlay" at 10200.49,7710 h60
  text "2" at 9790.58,7590 h60
  text "Top Solder" at 10200.49,7590 h60
  text "Solder Resist" at 11130.23,7590 h60
  text "0.40mil" at 11990,7590 h60
  text "3.5" at 12639.84,7590 h60
  text "3" at 9790.58,7470 h60
  text "Top Layer" at 10200.49,7470 h60
  text "Copper" at 11130.23,7470 h60
  text "1.40mil" at 11990,7470 h60
  text "4" at 9790.58,7350 h60
  text "Dielectric1" at 10200.49,7350 h60
  text "FR-4" at 11130.23,7350 h60
  text "59.20mil" at 11990,7350 h60
  text "4.8" at 12639.84,7350 h60
  text "5" at 9790.58,7230 h60
  text "Bottom Layer" at 10200.49,7230 h60
  text "Copper" at 11130.23,7230 h60
  text "1.40mil" at 11990,7230 h60
  text "6" at 9790.58,7110 h60
  text "Bottom Solder" at 10200.49,7110 h60
  text "Solder Resist" at 11130.23,7110 h60
  text "0.40mil" at 11990,7110 h60
  text "3.5" at 12639.84,7110 h60
  text "7" at 9790.58,6990 h60
  text "Bottom Overlay" at 10200.49,6990 h60
  text ".Layer_Name" at 577,-858.49 h60
M13 Component Bodies Top:
  text ".Layer_Name" at 577,-858.49 h60
M14 Component Bodies Bottom:
  text ".Layer_Name" at 577,-858.49 h60
M15 Courtyards Top:
  text ".Layer_Name" at 577,-858.49 h60
M16 Courtyards Bottom:
  text ".Layer_Name" at 577,-858.49 h60
Drill Drawing:
  circle w1: c5572.72,3221.04 r24.89
  lines w1: 5547.83,2598.88 5572.72,2611.32 5597.6,2598.88 5585.16,2623.76 5597.6,2648.65 5572.72,2636.21 5547.83,2648.65 5560.27,2623.76 5547.83,2598.88 ; 5547.83,2797.97 5597.6,2797.97 5572.72,2748.2 5547.83,2797.97 ; 5547.83,2909.96 5560.27,2909.96 5572.72,2897.52 5585.16,2909.96 5597.6,2909.96 5585.16,2922.4 5597.6,2934.85 5585.16,2934.85 5572.72,2947.29 5560.27,2934.85 5547.83,2934.85 5560.27,2922.4 5547.83,2909.96 ; 5547.83,3059.28 5560.27,3059.28 5560.27,3046.84 5585.16,3046.84 5585.16,3059.28 5597.6,3059.28 5597.6,3084.17 5585.16,3084.17 5585.16,3096.61 5560.27,3096.61 5560.27,3084.17 5547.83,3084.17 5547.83,3059.28
  lines w12: 5480,2554.08 7598.02,2554.08 ; 5480,3300.68 7598.02,3300.68 ; 5850.36,2404.76 5850.36,3450 ; 6207.36,2404.76 6207.36,3450 ; 6868.93,2404.76 6868.93,3450 ; 7153.07,2404.76 7153.07,3450 ; 5480,2404.76 7598.02,2404.76 7598.02,3450 5480,3450 5480,2404.76
  text "Symbol" at 5569.59,3345.48 h72
  text "Quantity" at 5895.16,3345.48 h72
  text "Finished Hole Size" at 6252.16,3345.48 h72
  text "Plated" at 6913.72,3345.48 h72
  text "Hole Type" at 7197.86,3345.48 h72
  text "5" at 5895.16,3196.16 h60
  text "7.87mil (0.200mm)" at 6252.16,3196.16 h60
  text "PTH" at 6913.72,3196.16 h60
  text "Round" at 7197.86,3196.16 h60
  text "68" at 5895.16,3046.84 h60
  text "16.00mil (0.406mm)" at 6252.16,3046.84 h60
  text "PTH" at 6913.72,3046.84 h60
  text "Round" at 7197.86,3046.84 h60
  text "8" at 5895.16,2897.52 h60
  text "40.00mil (1.016mm)" at 6252.16,2897.52 h60
  text "PTH" at 6913.72,2897.52 h60
  text "Round" at 7197.86,2897.52 h60
  text "6" at 5895.16,2748.2 h60
  text "41.34mil (1.050mm)" at 6252.16,2748.2 h60
  text "PTH" at 6913.72,2748.2 h60
  text "Round" at 7197.86,2748.2 h60
  text "4" at 5895.16,2598.88 h60
  text "50.00mil (1.270mm)" at 6252.16,2598.88 h60
  text "PTH" at 6913.72,2598.88 h60
  text "Round" at 7197.86,2598.88 h60
  text "91 Total" at 5895.16,2449.56 h60
  text ".Layer_Name" at 577,-858.49 h60

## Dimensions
0,-400 to 1000,-400 on M2 Board Dimensions
0,0 to 0,2250 on M2 Board Dimensions
0,0 to 2400,0 on M2 Board Dimensions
